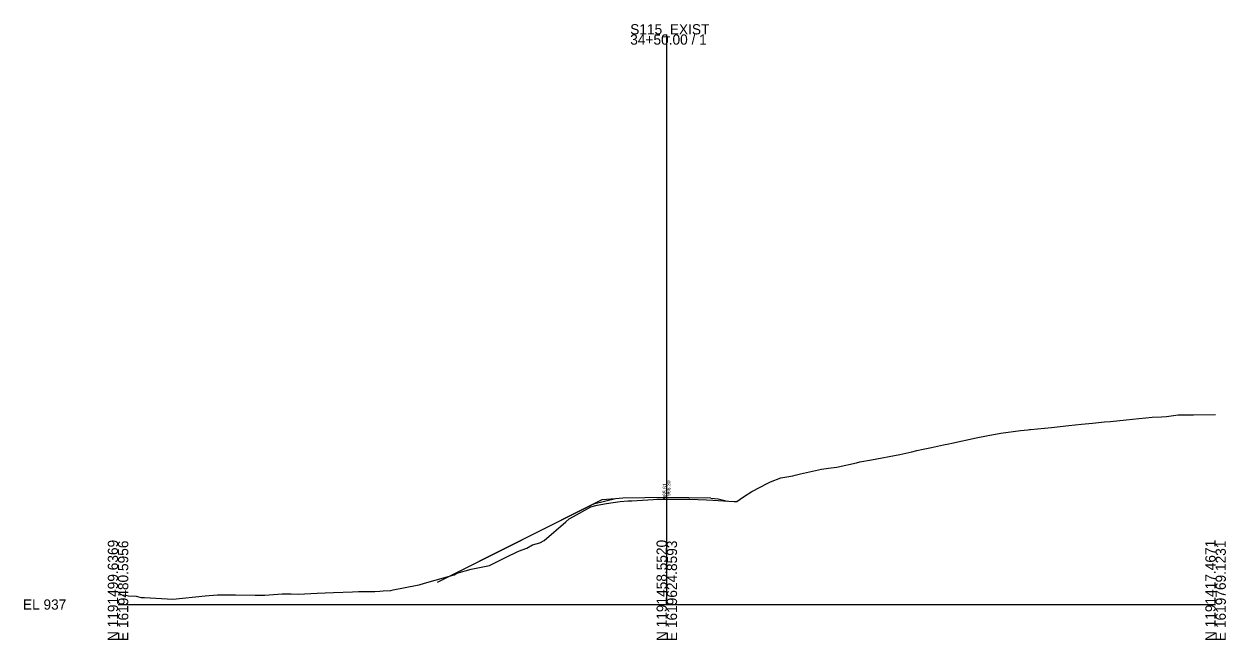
# Model space of a CAD drawing. Extents: x 1620351 to 1620680, y 1192592 to 1195749.
# Drawn here: x 1620351.1 to 1620679.6, y 1193091.8 to 1193260.2 of the extents above; entities that cross this region are included whole.
import ezdxf

# ---------------------------------------------------------------- set-up
doc = ezdxf.new("R2010")
doc.units = 0
for name, color, linetype in [('RD_GPK_XS_Cell', 7, 'Continuous'), ('RD_PD_SuperShp1', 7, 'Continuous'), ('RD_XS_EarthShd', 7, 'Continuous'), ('RD_XS_ExGround', 7, 'Continuous'), ('RD_XS_Pave', 7, 'Continuous'), ('RD_XS_TieSlope', 7, 'Continuous'), ('RD_XS_TX_Elev_EX', 7, 'Continuous'), ('RD_XS_TX_Elev_PR', 7, 'Continuous')]:
    doc.layers.add(name, color=color, linetype=linetype)

msp = doc.modelspace()

# ---------------------------------------------------------------- linework, layer by layer
at = {"layer": 'RD_GPK_XS_Cell'}
for p, q in [((1620526.76, 1193101.47), (1620526.76, 1193257.38)), ((1620376.76, 1193101.47), (1620526.76, 1193101.47)), ((1620526.76, 1193101.47), (1620676.76, 1193101.47))]:
    msp.add_line(p, q, dxfattribs=at)
at = {"layer": 'RD_PD_SuperShp1'}
for p, q in [((1620509.01, 1193130.07), (1620463.95, 1193107.53)), ((1620512.76, 1193130.37), (1620509.01, 1193130.07))]:
    msp.add_line(p, q, dxfattribs=at)
at = {"layer": 'RD_XS_EarthShd'}
for p, q in [((1620514.76, 1193130.53), (1620512.76, 1193130.37)), ((1620538.76, 1193130.53), (1620540.76, 1193130.37))]:
    msp.add_line(p, q, dxfattribs=at)
at = {"layer": 'RD_XS_ExGround'}
msp.add_lwpolyline([(1620376.76, 1193104.17), (1620378.85, 1193103.99), (1620379.58, 1193103.85), (1620381.71, 1193103.74), (1620383.12, 1193103.42), (1620384.02, 1193103.37), (1620391.72, 1193102.89), (1620400.55, 1193103.87), (1620403.96, 1193104.09), (1620406.52, 1193104.13), (1620408.86, 1193104.08), (1620414.22, 1193104.04), (1620416.85, 1193104.06), (1620421.65, 1193104.36), (1620424.09, 1193104.41), (1620425.96, 1193104.3), (1620431.18, 1193104.57), (1620433.4, 1193104.71), (1620435.69, 1193104.8), (1620440.87, 1193104.98), (1620442.46, 1193104.99), (1620446.99, 1193105.04), (1620448.33, 1193105.1), (1620449.19, 1193105.19), (1620451.3, 1193105.34), (1620451.94, 1193105.47), (1620458.54, 1193106.76), (1620459.03, 1193106.87), (1620460.5, 1193107.29), (1620468.61, 1193109.62), (1620469.41, 1193110.02), (1620473.28, 1193111.14), (1620473.72, 1193111.27), (1620478.29, 1193112.17), (1620479, 1193112.52), (1620482.65, 1193114.29), (1620486.25, 1193116.06), (1620488.48, 1193116.84), (1620490.09, 1193117.78), (1620492.01, 1193118.35), (1620493.28, 1193118.96), (1620499.13, 1193124.07), (1620500.07, 1193124.88), (1620501.22, 1193125.57), (1620505.98, 1193128.15), (1620507.69, 1193128.6), (1620510.24, 1193129.07), (1620512.06, 1193129.41), (1620514.05, 1193129.65), (1620516.13, 1193129.8), (1620517.24, 1193129.81), (1620523.05, 1193130.19), (1620524.03, 1193130.26), (1620524.6, 1193130.27), (1620526.76, 1193130.27), (1620530.74, 1193130.28), (1620533.07, 1193130.26), (1620537.58, 1193130.08), (1620539.37, 1193129.98), (1620545.17, 1193129.6), (1620545.93, 1193129.68), (1620547.7, 1193130.9), (1620550.02, 1193132.4), (1620554.4, 1193134.7), (1620555.09, 1193135.02), (1620557.94, 1193136.14), (1620561.17, 1193136.69), (1620561.89, 1193136.88), (1620562.2, 1193136.93), (1620563.3, 1193137.18), (1620569.05, 1193138.49), (1620571, 1193138.72), (1620573.28, 1193139.07), (1620573.64, 1193139.14), (1620578.63, 1193140.25), (1620579.52, 1193140.45), (1620582.69, 1193141.05), (1620590.44, 1193142.51), (1620593.75, 1193143.22), (1620595.07, 1193143.56), (1620596.79, 1193143.99), (1620599.14, 1193144.45), (1620602.43, 1193145.1), (1620603.86, 1193145.45), (1620604.63, 1193145.64), (1620611.33, 1193147.02), (1620614.61, 1193147.7), (1620618.06, 1193148.29), (1620623.44, 1193149.02), (1620625.41, 1193149.24), (1620625.87, 1193149.3), (1620626.19, 1193149.33), (1620631.89, 1193149.89), (1620636.68, 1193150.4), (1620640.12, 1193150.76), (1620643.16, 1193151.08), (1620646.44, 1193151.4), (1620648.04, 1193151.49), (1620652.28, 1193151.98), (1620655.74, 1193152.33), (1620657.73, 1193152.51), (1620659.47, 1193152.67), (1620661.99, 1193152.81), (1620663.36, 1193152.92), (1620666.51, 1193153.3), (1620670.75, 1193153.36), (1620676.76, 1193153.44)], dxfattribs=at)
at = {"layer": 'RD_XS_Pave'}
for p, q in [((1620526.76, 1193130.77), (1620514.76, 1193130.53)), ((1620538.76, 1193130.53), (1620526.76, 1193130.77))]:
    msp.add_line(p, q, dxfattribs=at)
at = {"layer": 'RD_XS_TieSlope'}
for p, q in [((1620506.76, 1193128.87), (1620467.82, 1193109.4)), ((1620512.76, 1193130.37), (1620506.76, 1193128.87)), ((1620540.76, 1193130.37), (1620543.36, 1193129.72))]:
    msp.add_line(p, q, dxfattribs=at)

# ---------------------------------------------------------------- texts
at = {"layer": 'RD_GPK_XS_Cell'}
for s, p in [('S115_EXIST', (1620516.76, 1193257.38)), ('34+50.00 / 1', (1620516.76, 1193254.58)), ('EL 937', (1620350.76, 1193100.07))]:
    msp.add_text(s, height=2.8, dxfattribs=at).set_placement(p)
for s, p in [('N 1191499.6369', (1620376.76, 1193091.47)), ('E 1619480.5956', (1620379.56, 1193091.47)), ('N 1191458.5520', (1620526.76, 1193091.47)), ('E 1619624.8593', (1620529.56, 1193091.47)), ('N 1191417.4671', (1620676.76, 1193091.47)), ('E 1619769.1231', (1620679.56, 1193091.47))]:
    msp.add_text(s, height=2.8, rotation=90, dxfattribs=at).set_placement(p)
at = {"layer": 'RD_XS_TX_Elev_EX'}
msp.add_text('965.81', height=1, rotation=90, dxfattribs=at).set_placement((1620526.66, 1193130.37))
at = {"layer": 'RD_XS_TX_Elev_PR'}
msp.add_text(' 966.30', height=1, rotation=90, dxfattribs=at).set_placement((1620527.76, 1193130.77))

doc.saveas('drawing.dxf')
